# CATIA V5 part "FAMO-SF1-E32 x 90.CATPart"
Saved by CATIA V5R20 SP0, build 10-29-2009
Part number: FAMO-SF1-E32 x 90
Definition: NONE
Nomenclature: FAMO-SF1-E32 x 90
Source: Unknown
Description: FAMO-SF1-E32 x 90
Bounding box of the stored display mesh (mm): x -64 to 26, y -26.5 to 26.5, z -26.5 to 26.5
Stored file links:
  C:\Users\Utente\Desktop\IO LAVORO\3D X SITO CF\X SITO\FAMO\FAMO-SF1-E32 x 90.CATPart
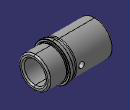
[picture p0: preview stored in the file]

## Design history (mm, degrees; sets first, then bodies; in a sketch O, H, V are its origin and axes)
Body1 "FAMO-SF1-E32 x 90" (main body)
  Solid1: solid without history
